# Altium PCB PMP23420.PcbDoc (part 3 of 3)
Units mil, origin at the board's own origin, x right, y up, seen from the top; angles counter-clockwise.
Board outline 5200 x 3400 mil, 6 copper layers (Top Layer, Midlayer 1, Midlayer 2, Midlayer 3, Midlayer 4, Bottom Layer), stack 61.536 mil thick; 227 components, 56 nets, 480 pads, 964 vias.
Unrouted connection lines stored in the file: 22.
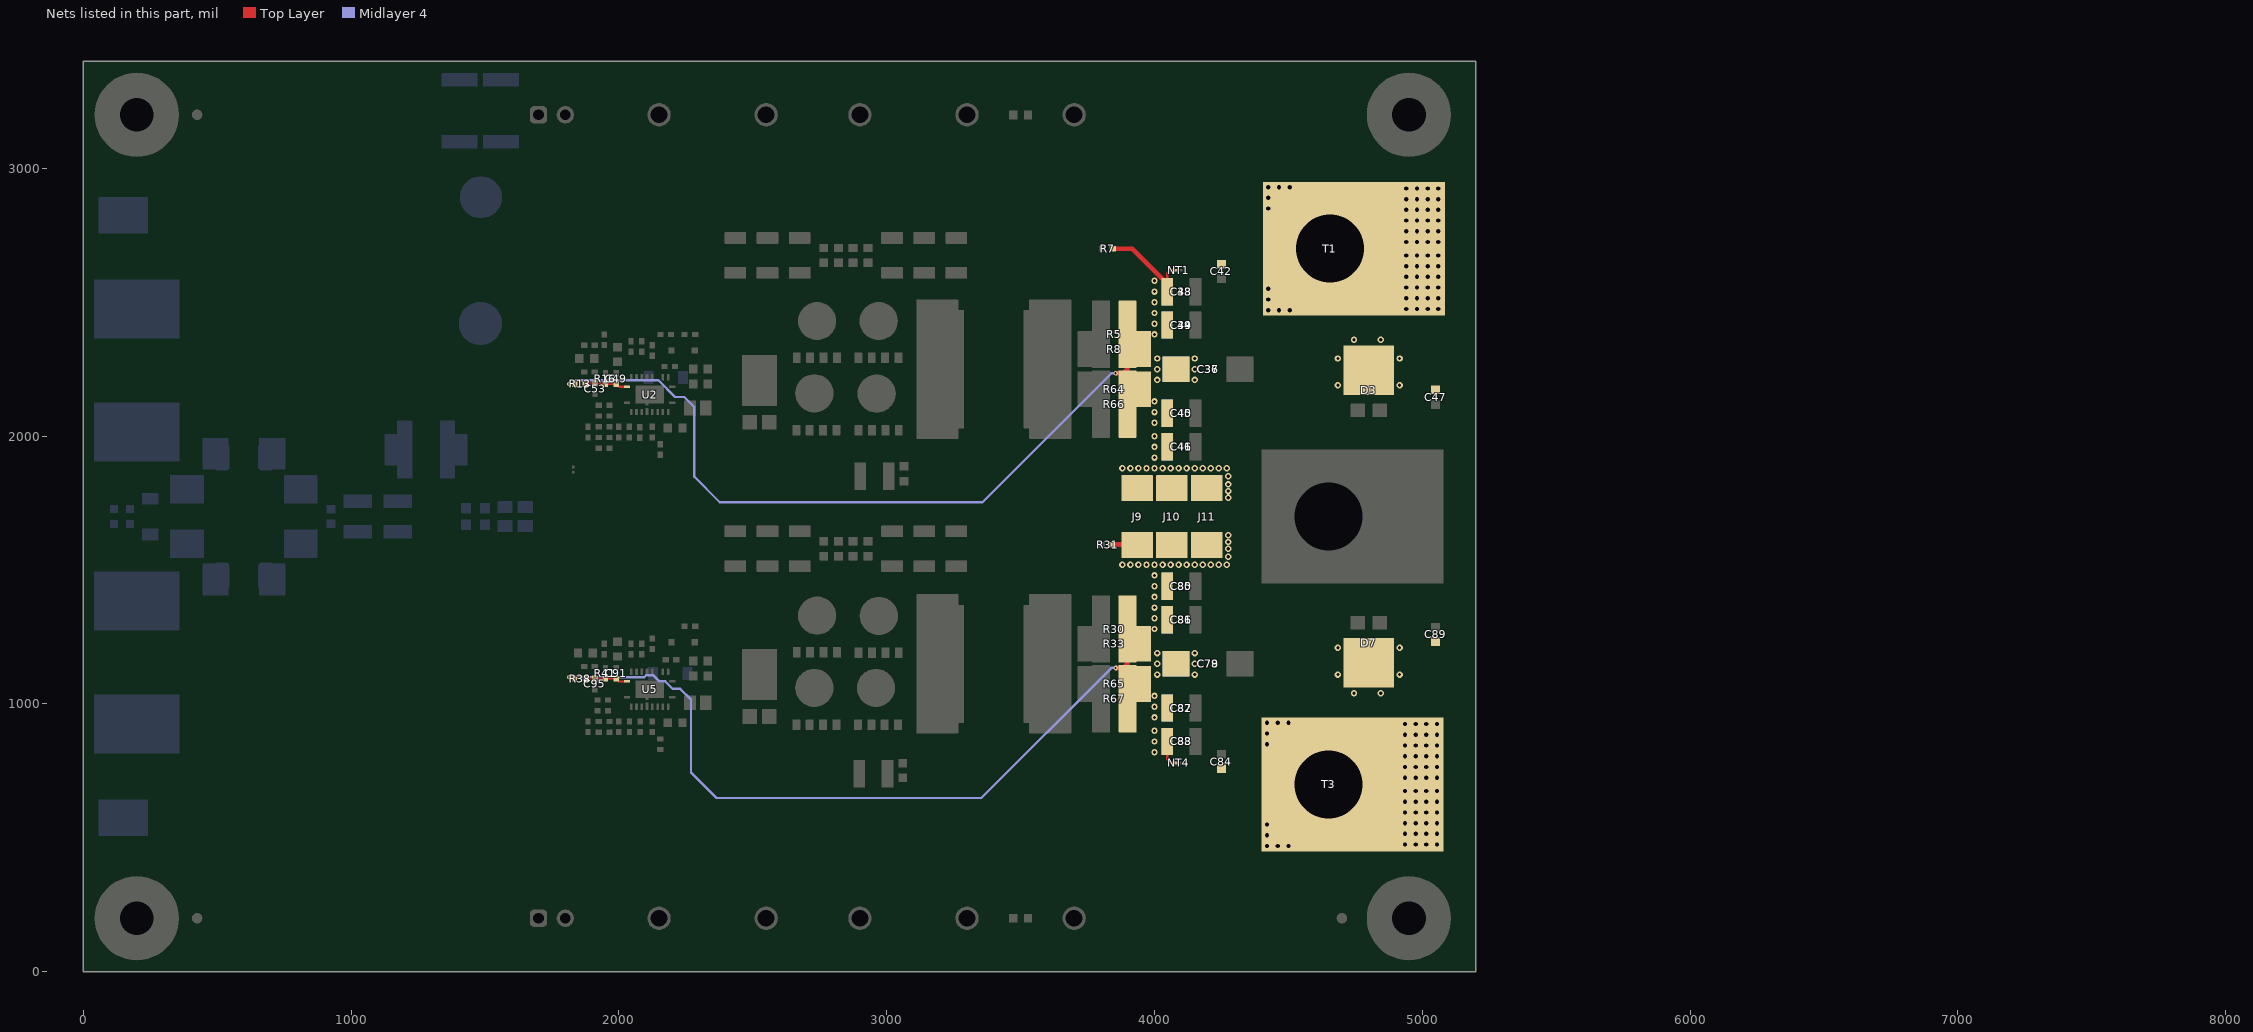
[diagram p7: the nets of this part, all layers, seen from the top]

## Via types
v1: diameter 24, hole 12, Top Layer to Bottom Layer, tented both sides, 565 vias
v2: diameter 32, hole 16, Top Layer to Bottom Layer, 174 vias
v3: diameter 18, hole 8, Top Layer to Bottom Layer, tented bottom, 88 vias
v4: diameter 18, hole 8, Top Layer to Bottom Layer, tented both sides, 71 vias
v5: diameter 24, hole 12, Top Layer to Bottom Layer, tented top, 58 vias
v6: diameter 19.68, hole 7.87, Top Layer to Bottom Layer, tented both sides, 8 vias

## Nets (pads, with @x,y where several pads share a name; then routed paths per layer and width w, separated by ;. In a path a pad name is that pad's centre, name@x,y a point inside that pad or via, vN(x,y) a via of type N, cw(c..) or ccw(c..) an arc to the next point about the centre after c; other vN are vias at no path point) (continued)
VOUT1: C36.1 C37.1 C38.1 C39.1 C40.1 C41.1 C42.1 C43.1 C44.1 C45.1 C46.1 C47.1 D3.3 J9.2 J10.2 J11.2 NT1.2 R5.2 R7.1 R8.2 R13.2 R64.2 R66.2 T1.1 | length 3018.9
  Top Layer w9: v4(1815,2195) R13.2@1835.32,2195 ; C38.1@4046.85,2540 4046.85,2569.53 4046.85,2607.11 4059.74,2620 NT1.2@4080,2620
  Top Layer w18: R7.1@3844.69,2700 3916.38,2700 C38.1@4046.85,2569.53 ; v4(3855,2235) 3884.21,2235 3899.21,2250
  Midlayer 4 w9: v4(1815,2195) 1825.16,2195 1839.15,2208.99 2147.37,2208.99 2209.99,2146.37 2244.38,2146.37 2281.58,2109.18 2281.58,1848.84 2376.87,1753.55 3357.41,1753.55 3838.86,2235 v4(3855,2235)
  other v1: 4275,1770 4275,1795 4275,1820 4275,1850 3880,1880 3910,1880 3940,1880 3970,1880 4000,1880 4030,1880 4060,1880 4090,1880 4120,1880 4150,1880 4180,1880 4210,1880 4240,1880 4270,1880 4000,1920 4000,1960 4000,2000 4000,2050 4000,2090 4000,2130 4685,2190 4915,2190 4010,2210 4150,2210 4010,2250 4150,2250 4010,2290 4150,2290 4685,2290 4915,2290 4745,2360 4845,2360 4000,2380 4000,2420 4000,2460 4000,2500 4000,2540 4000,2580
  other v2: 4425,2470 4465,2470 4505,2470 4940,2475 4980,2475 5020,2475 5060,2475 4425,2510 4940,2515 4980,2515 5020,2515 5060,2515 4425,2550 4940,2555 4980,2555 5020,2555 5060,2555 4940,2595 4980,2595 5020,2595 5060,2595 4940,2635 4980,2635 5020,2635 5060,2635 4940,2675 4980,2675 5020,2675 5060,2675 4940,2725 4980,2725 5020,2725 5060,2725 4940,2765 4980,2765 5020,2765 5060,2765 4940,2805 4980,2805 5020,2805 5060,2805 4940,2845 4980,2845 5020,2845 5060,2845 4425,2850 4940,2885 4980,2885 5020,2885 5060,2885 4425,2890 4940,2925 4980,2925 5020,2925 5060,2925 4425,2930 4465,2930 4505,2930
VOUT2: C78.1 C79.1 C80.1 C81.1 C82.1 C83.1 C84.1 C85.1 C86.1 C87.1 C88.1 C89.1 D7.3 J9.1 J10.1 J11.1 NT4.2 R30.2 R31.2 R33.2 R38.2 R65.2 R67.2 T3.1 | length 2862.5
  Top Layer w9: v4(1815,1100) 1816.72,1098.28 1832.04,1098.28 R38.2@1835.32,1095 ; J9.1@3934.19,1595 J9.1@3935,1594.19 ; C83.1@4046.85,860 4046.85,795.2 4062.05,780 NT4.2@4080,780
  Top Layer w18: R31.2@3844.69,1595 J9.1@3934.19,1595 ; v4(3855,1135) 3884.21,1135 3899.21,1150
  Midlayer 4 w9: v4(1815,1100) 1835.32,1100 1835.44,1099.88 2094.76,1099.88 2102.85,1107.96 2127.15,1107.96 2149.61,1085.5 2149.61,1084.34 2173.2,1084.34 2200.93,1056.62 2229.04,1056.62 2269.41,1016.25 2269.41,744.43 2364.87,648.98 3352.84,648.98 3838.86,1135 v4(3855,1135)
  other v1: 4000,820 4000,860 4000,900 4000,950 4000,990 4000,1030 4745,1040 4845,1040 4010,1110 4150,1110 4685,1110 4915,1110 4010,1150 4150,1150 4010,1190 4150,1190 4685,1210 4915,1210 4000,1280 4000,1320 4000,1360 4000,1400 4000,1440 4000,1480 3880,1520 3910,1520 3940,1520 3970,1520 4000,1520 4030,1520 4060,1520 4090,1520 4120,1520 4150,1520 4180,1520 4210,1520 4240,1520 4270,1520 4275,1550 4275,1580 4275,1605 4275,1630
  other v2: 4420,470 4460,470 4500,470 4935,475 4975,475 5015,475 5055,475 4420,510 4935,515 4975,515 5015,515 5055,515 4420,550 4935,555 4975,555 5015,555 5055,555 4935,595 4975,595 5015,595 5055,595 4935,635 4975,635 5015,635 5055,635 4935,675 4975,675 5015,675 5055,675 4935,725 4975,725 5015,725 5055,725 4935,765 4975,765 5015,765 5055,765 4935,805 4975,805 5015,805 5055,805 4935,845 4975,845 5015,845 5055,845 4420,850 4935,885 4975,885 5015,885 5055,885 4420,890 4935,925 4975,925 5015,925 5055,925 4420,930 4460,930 4500,930
VOUTsns1: C49.1 C53.2 R13.1 R16.1 U2.20 | length 158.4
  Top Layer w8: R13.1@1874.68,2195 1876.03,2196.34 1909.66,2196.34 C53.2@1911,2197.69 ; C53.2@1914.84,2195.16 1949.84,2195.16 R16.1@1950,2195.31 C49.1@1989.84,2195.31 ; C49.1@1989.84,2195.16 1989.84,2193.5 1995.84,2187.5 1997.5,2187.5 2000.47,2184.53 U2.20@2030.35,2184.53
VOUTsns2: C91.1 C95.2 R38.1 R41.1 U5.20 | length 156.9
  Top Layer w8: R38.1@1874.68,1095 1874.84,1094.84 1909.84,1094.84 C95.2@1910,1094.69 ; C95.2@1914.84,1095.16 1949.84,1095.16 R41.1@1950,1095.32 C91.1@1990,1095.32 C91.1@1990,1093.35 ; C91.1@1989.84,1093.19 C91.1@1990,1093.35 ; U5.20@2030.35,1084.53 1998.82,1084.53 C91.1@1990,1093.35
pads on no net: FID1.1 FID2.1 FID3.1 FID4.1 FID5.1 FID6.1 H1.1 H2.1 H3.1 H4.1 H5.0 H6.0 H7.0 H8.0 LBL1.0 SH-J1.0 SH-J2.0

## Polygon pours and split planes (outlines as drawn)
VIN on Top Layer "TOP_LAYER_Vin_Phase2" (solid, remove dead copper, pour order 71): 2624.74,1250.08 2624.74,1430.08 2589.74,1465.08 2359.74,1465.08 2359.74,1570.08 3334.74,1570.08 3334.74,1465.08 3114.74,1465.08 3079.74,1430.08 3079.74,1250.08
SW2 on Top Layer "TOP_LAYER_SW2" (solid, remove dead copper, pour order 72): 3070,1170 3070,1215 3100,1215 3100,1410 3270,1410 3270,885 3100,885 3100,955 3075,980 2620,980 2620,1005 2450,1005 2450,1215 2790,1215 2790,1170 2870,1170 2870,1215 3020,1215 3020,1170
GNDin on Top Layer "TOP_LAYER_GND_IN" (solid, remove dead copper, pour order 34): 399.45,1149.82 399.45,799.82 299.45,699.82 299.45,474.82 -0.55,474.82 -0.55,1149.82 -0.99,1149.82 -0.99,1684.82 194.01,1684.82 194.01,1655.56 454.01,1655.56 454.01,1530.56 549.01,1530.56 549.01,1149.82
+Vin_Main on Top Layer "TOP_LAYER_+Vin_Main" (solid, remove dead copper, pour order 33): 399.66,2250.58 399.66,2600.58 299.66,2700.58 299.66,2925.58 -0.34,2925.58 -0.34,1715.58 194.66,1715.58 194.66,1745.58 454.66,1745.58 454.66,1870.58 549.66,1870.58 549.66,2250.58
+Filter on Top Layer "TOP_LAYER_+Filter" (solid, remove dead copper, pour order 35): 648.74,1870.69 743.74,1870.69 743.74,1745.69 899.71,1745.69 899.71,1715.19 1234.71,1715.19 1234.71,2100.19 648.74,2100.19
VOUT2 on Top Layer "TOP_LAYER_VOUT2" (solid, remove dead copper, pour order 74): 4400,975 4675,1250 5100,1250 5100,440 3865,440 3865,1645 4290,1645 4290,1507 4085,1507 4085,1260 4115,1230 4145,1230 4175,1200 4175,1100 4145,1070 4115,1070 4085,1040 4085,775 4400,775
GND on Top Layer "TOP_LAYER_GND" (solid, remove dead copper, pour order 76): 650,1150 650,1530 745,1530 745,1655 900,1655 900,1685 1275,1685 1275,3400 5200,3400 5200,0 1325,0 1325,1150
VOUT1 on Top Layer "TOP_LAYER_VOUT1" (solid, remove dead copper, pour order 73): 4392.8,2423.55 4667.8,2148.55 5100,2148.55 5100,2958.55 3865,2958.55 3865,1753.55 4290,1753.55 4290,1893 4077.8,1893 4077.8,2138.55 4107.8,2168.55 4137.8,2168.55 4167.8,2198.55 4167.8,2298.55 4137.8,2328.55 4107.8,2328.55 4077.8,2358.55 4077.8,2623.55 4392.8,2623.55
VCC2 on Top Layer "TOP_LAYER_VCC1" (solid, remove dead copper, pour order 49): 2140,1000 2150,1000 2150,970 2170,950 2200,950 2200,910 2170,910 2140,940 2140,965
VCC1 on Top Layer "TOP_LAYER_VCC1" (solid, remove dead copper, pour order 37): 2140,2100 2150,2100 2150,2070 2170,2050 2200,2050 2200,2010 2170,2010 2140,2040 2140,2065
AGND2 on Top Layer "TOP_LAYER_AGND2" (solid, remove dead copper, pour order 43): 2135,910 2070,910 2070,875 1935,875 1935,1030 1815,1030 1815,780 2135,780
AGND1 on Top Layer "TOP_LAYER_AGND1" (solid, remove dead copper, pour order 36): 2135,2010 2070,2010 2070,1975 1935,1975 1935,2130 1815,2130 1815,1880 2135,1880
SW1 on Top Layer "TOP_LAYER_SW1" (solid, remove dead copper, pour order 39): 3070,2270 3070,2315 3100,2315 3100,2510 3270,2510 3270,1985 3100,1985 3100,2055 3075,2080 2620,2080 2620,2105 2450,2105 2450,2315 2790,2315 2790,2270 2870,2270 2870,2315 3020,2315 3020,2270
VIN on Top Layer "TOP_LAYER_Vin_Phase1" (solid, remove dead copper, pour order 38): 2625,2345 2625,2525 2590,2560 2360,2560 2360,2665 3335,2665 3335,2560 3115,2560 3080,2525 3080,2345
GNDin on Midlayer 2 "MIDLAYER_2_GND_IN" (solid, remove dead copper, pour order 42): 399.64,1150.3 399.64,800.3 299.64,700.3 299.64,475.3 -0.36,475.3 -0.36,1150.3 -0.8,1150.3 -0.8,1685.3 194.2,1685.3 194.2,1656.04 454.2,1656.04 454.2,1531.04 549.2,1531.04 549.2,1150.3
+Vin_Main on Midlayer 2 "MIDLAYER_2_+Vin_Main" (solid, remove dead copper, pour order 32): 399.72,2250.48 399.72,2600.48 299.72,2700.48 299.72,2925.48 -0.28,2925.48 -0.28,1715.48 194.72,1715.48 194.72,1745.48 454.72,1745.48 454.72,1870.48 549.72,1870.48 549.72,2250.48
+Filter on Midlayer 2 "MIDLAYER_2_+Filter" (solid, remove dead copper, pour order 44): 649.03,1870.5 744.03,1870.5 744.03,1745.5 900,1745.5 900,1715 1235,1715 1235,2100 649.03,2100
GND on Midlayer 2 "MIDLAYER_2_GND" (solid, remove dead copper, pour order 66): 650,1150 1325,1150 1325,0.88 5200,0.88 5200,3400.88 1275,3400.88 1275,1685 900,1685 900,1655 745,1655 745,1530 650,1530
VIN on Midlayer 2 "MIDLAYER_2_VIN" (solid, remove dead copper, pour order 60): 1535,750 1535,1505 1325,1715 1325,2840 3355,2840 3355,750
VOUT1 on Midlayer 2 "MIDLAYER_2_VOUT1" (solid, remove dead copper, pour order 64): 4392.5,2422.5 4667.5,2147.5 5100,2147.5 5100,2957.5 3865,2957.5 3865,1752.5 4290,1752.5 4290,1895 4077.5,1895 4077.5,2137.5 4107.5,2167.5 4137.5,2167.5 4167.5,2197.5 4167.5,2297.5 4137.5,2327.5 4107.5,2327.5 4077.5,2357.5 4077.5,2622.5 4392.5,2622.5
VOUT2 on Midlayer 2 "MIDLAYER_2_VOUT2" (solid, remove dead copper, pour order 65): 4400,975 4675,1250 5100,1250 5100,440 3865,440 3865,1645 4290,1645 4290,1505 4085,1505 4085,1260 4115,1230 4145,1230 4175,1200 4175,1100 4145,1070 4115,1070 4085,1040 4085,775 4400,775
VIN on Bottom Layer "BOTTOM_LAYER_Vin_Phase2" (solid, remove dead copper, pour order 57): 2625,1250 2625,1430 2590,1465 2360,1465 2360,1570 3335,1570 3335,1465 3115,1465 3080,1430 3080,1250
VIN on Bottom Layer "BOTTOM_LAYER_Vin_Phase1" (solid, remove dead copper, pour order 56): 2624.94,2345.22 2624.94,2525.22 2589.94,2560.22 2359.94,2560.22 2359.94,2665.22 3334.94,2665.22 3334.94,2560.22 3114.94,2560.22 3079.94,2525.22 3079.94,2345.22
+Filter on Bottom Layer "BOTTOM_LAYER_+Filter" (solid, remove dead copper, pour order 48): 648.28,1870.96 743.28,1870.96 743.28,1745.96 899.25,1745.96 899.25,1715 1235,1715 1235,2100.46 648.28,2100.46
VOUT2 on Bottom Layer "BOTTOM_LAYER_VOUT2" (solid, remove dead copper, pour order 70): 4400,975 4675,1250 5100,1250 5100,440 3865,440 3865,1645 4260,1645 4260,1535 4085,1535 4085,1260 4115,1230 4145,1230 4175,1200 4175,1100 4145,1070 4115,1070 4085,1040 4085,775 4400,775
VOUT1 on Bottom Layer "BOTTOM_LAYER_VOUT1" (solid, remove dead copper, pour order 63): 4392.8,2423.55 4667.8,2148.55 5100,2148.55 5100,2958.55 3865,2958.55 3865,1753.55 4257.8,1753.55 4257.8,1863.55 4077.8,1863.55 4077.8,2138.55 4107.8,2168.55 4137.8,2168.55 4167.8,2198.55 4167.8,2298.55 4137.8,2328.55 4107.8,2328.55 4077.8,2358.55 4077.8,2623.55 4392.8,2623.55
GND on Bottom Layer "BOTTOM_LAYER_GND" (solid, remove dead copper, pour order 75): 650,1150 1325,1150 1325,0 5200,0 5200,3400 1275,3400 1275,1685 899.33,1685 899.33,1655.08 745,1655.08 745,1530.08 650,1530.08
GNDin on Bottom Layer "BOTTOM_LAYER_GND_IN" (solid, remove dead copper, pour order 47): 400,1150 400,800 300,700 300,475 0,475 0,1150 -0.44,1150 -0.44,1685 194.56,1685 194.56,1655.74 454.56,1655.74 454.56,1530.74 549.56,1530.74 549.56,1150
+Vin_Main on Bottom Layer "BOTTOM_LAYER_+Vin_Main" (solid, remove dead copper, pour order 45): 400,2250 400,2600 300,2700 300,2925 0,2925 0,1715 195,1715 195,1745 455,1745 455,1870 550,1870 550,2250
GNDin on Midlayer 4 "MIDLAYER_4_GND_IN" (solid, remove dead copper, pour order 51): 400,1150 400,800 300,700 300,475 0,475 0,1150 -0.44,1150 -0.44,1685 194.56,1685 194.56,1655.74 454.56,1655.74 454.56,1530.74 549.56,1530.74 549.56,1150
+Filter on Midlayer 4 "MIDLAYER_4_+Filter" (solid, remove dead copper, pour order 58): 648.47,1870.89 743.47,1870.89 743.47,1745.89 899.44,1745.89 899.44,1715 1235,1715 1235,2100.39 648.47,2100.39
GND on Midlayer 4 "MIDLAYER_4_GND" (solid, remove dead copper, pour order 62): 650,1150.44 1325,1150.44 1325,0.44 5200,0.44 5200,3400.44 1275,3400.44 1275,1685 899.07,1685 899.07,1655.52 745,1655.52 745,1530.52 650,1530.52
+Vin_Main on Midlayer 4 "MIDLAYER_4_+Vin_Main" (solid, remove dead copper, pour order 50): 400,2250 400,2600 300,2700 300,2925 0,2925 0,1715 195,1715 195,1745 455,1745 455,1870 550,1870 550,2250
GNDin on Midlayer 3 "MIDLAYER_3_GND_IN" (solid, remove dead copper, pour order 52): 400,1150 400,800 300,700 300,475 0,475 0,1150 -0.44,1150 -0.44,1685 194.56,1685 194.56,1655.74 454.56,1655.74 454.56,1530.74 549.56,1530.74 549.56,1150
+Filter on Midlayer 3 "MIDLAYER_3_+Filter" (solid, remove dead copper, pour order 53): 649.03,1870.5 744.03,1870.5 744.03,1745.5 900,1745.5 900,1715 1235,1715 1235,2100 649.03,2100
GND on Midlayer 3 "MIDLAYER_3_GND" (solid, remove dead copper, pour order 59): 650,1150.06 1325,1150.06 1325,0.06 5200,0.06 5200,3400.06 1275,3400.06 1275,1685 898.86,1685 898.86,1655.15 745,1655.15 745,1530.15 650,1530.15
+Vin_Main on Midlayer 3 "MIDLAYER_3_+Vin_Main" (solid, remove dead copper, pour order 46): 400,2250 400,2600 300,2700 300,2925 0,2925 0,1715 195,1715 195,1745 455,1745 455,1870 550,1870 550,2250
GNDin on Midlayer 1 "MIDLAYER_1_GND_IN" (solid, remove dead copper, pour order 67): 399.46,1149.97 399.46,799.97 299.46,699.97 299.46,474.97 -0.54,474.97 -0.54,1149.97 -0.99,1149.97 -0.99,1684.97 194.01,1684.97 194.01,1655.71 454.01,1655.71 454.01,1530.71 549.01,1530.71 549.01,1149.97
+Vin_Main on Midlayer 1 "MIDLAYER_1_+Vin_Main" (solid, remove dead copper, pour order 61): 399.68,2250.58 399.68,2600.58 299.68,2700.58 299.68,2925.58 -0.32,2925.58 -0.32,1715.58 194.68,1715.58 194.68,1745.58 454.68,1745.58 454.68,1870.58 549.68,1870.58 549.68,2250.58
+Filter on Midlayer 1 "MIDLAYER_1_+Filter" (solid, remove dead copper, pour order 68): 648.8,1870.66 743.8,1870.66 743.8,1745.66 899.77,1745.66 899.77,1715.16 1234.77,1715.16 1234.77,2100.16 648.8,2100.16
GND on Midlayer 1 "MIDLAYER_1_GND" (solid, remove dead copper, pour order 69): 650,1150 1325,1150 1325,2.26 5200,2.26 5200,3402.26 1275,3402.26 1275,1685 900,1685 900,1655 745,1655 745,1530 650,1530

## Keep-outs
Keep-Out Layer:
  text ".Layer_Name" at 577,-858.49 h60

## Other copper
Top Layer:
  rectangle net GND: 2460,890 2590,980
  rectangle net GND: 2460,1990 2590,2080
  pour cut-out: 3062.54,946.07 3062.54,961.07 3017.54,961.07 3017.54,946.07
  pour cut-out: 3065,2045 3065,2060 3020,2060 3020,2045
  pour cut-out: 3069.18,2261.07 3079.18,2271.07 3079.18,2316.07 3009.18,2316.07 3009.18,2271.07 3019.18,2261.07
  pour cut-out: 2839.18,2261.07 2849.18,2271.07 2849.18,2316.07 2779.18,2316.07 2779.18,2271.07 2789.18,2261.07
  pour cut-out: 2839.18,1161.07 2849.18,1171.07 2849.18,1216.07 2779.18,1216.07 2779.18,1171.07 2789.18,1161.07
  pour cut-out: 3070,1160 3080,1170 3080,1215 3010,1215 3010,1170 3020,1160
  pour cut-out: 2174,2332 2232,2332 2232,2280 2306,2280 2306,2360 2184,2360 2165,2341 2141,2341 2141,2226 2130,2215 2130,2190 2160,2190 2160,2271 2174,2285
  pour cut-out: 2306,1200 2240,1200 2240,1244 2182,1244 2160,1222 2160,1090 2130,1090 2130,1115 2144.84,1129.84 2144.84,1240.84 2177,1273 2306,1273
  pour cut-out: 2360,2663 3335,2663 3335,2687 2360,2687
  pour cut-out: 2360,1568 3335,1568 3335,1592 2360,1592
  pour cut-out: 3835,1420 3865,1420 3865,880 3835,880
  pour cut-out: 3835,2520 3865,2520 3865,1980 3835,1980
  pour cut-out: 3120,1415 3120,1460 3680,1460 3680,1415 3505,1415 3505,885 3680,885 3680,840 3120,840 3120,880 3295,880 3295,1415
  pour cut-out: 3120,2515 3120,2560 3680,2560 3680,2515 3505,2515 3505,1985 3680,1985 3680,1940 3120,1940 3120,1980 3295,1980 3295,2515
  region net NetL4_2: 3835,1990 3530,1990 3530,2510 3835,2510
  region net NetL6_2: 3835,890 3530,890 3530,1410 3835,1410
  text ".Layer_Name" at 577,-858.49 h60
Bottom Layer:
  rectangle net NetC1_1: 1325,2765 1645,3130
  pour cut-out: 1315,1715 1315,1685 1710,1685 1710,1715 1540,1715
  pour cut-out: 2360,1568 3335,1568 3335,1592 2360,1592
  pour cut-out: 2360,2663 3335,2663 3335,2687 2360,2687
  pour cut-out: 1645,3010 1830,3010 1830,2305 1690,2305 1690,2575 1305,2575 1305,2765 1645,2765
  region net VIN: 1325,1715 1325,2575 1690,2575 1690,1715
  text ".Layer_Name" at 577,-858.49 h60

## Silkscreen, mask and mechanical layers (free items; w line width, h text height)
Top Overlay:
  lines w5.91: 3127.28,2525.28 3127.28,2549.21 ; 3132.28,1425.28 3132.28,1449.21 ; 3668,1425 3668,1448.93 ; 3668,2525 3668,2548.93
  lines w6: 1853,1086 1857,1086 ; 1853,1104 1857,1104 ; 1853,2186 1857,2186 ; 1853,2204 1857,2204 ; 1876,913 1876,917 ; 1876,2013 1876,2017 ; 1888,1131 1892,1131 ; 1888,1149 1892,1149 ; 1888,2231 1892,2231 ; 1888,2249 1892,2249 ; 1888,2331 1892,2331 ; 1888,2349 1892,2349 ; 1894,913 1894,917 ; 1894,2013 1894,2017 ; 1901,1073 1901,1077 ; 1902,2176 1902,2180 ; 1919,1073 1919,1077 ; 1920,2176 1920,2180 ; 1936,1203 1936,1207 ; 1936,2358 1936,2362 ; 1938,966 1942,966 ; 1938,984 1942,984 ; 1938,1006 1942,1006 ; 1938,1024 1942,1024 ; 1941,1113 1941,1117 ; 1941,2213 1941,2217 ; 1943,886 1947,886 ; 1943,904 1947,904 ; 1943,926 1947,926 ; 1943,944 1947,944 ; 1943,1946 1947,1946 ; 1943,1964 1947,1964 ; 1943,1986 1947,1986 ; 1943,2004 1947,2004 ; 1943,2026 1947,2026 ; 1943,2044 1947,2044 ; 1943,2066 1947,2066 ; 1943,2084 1947,2084 ; 1943,2106 1947,2106 ; 1943,2124 1947,2124 ; 1954,1203 1954,1207 ; 1954,2358 1954,2362 ; 1959,1113 1959,1117 ; 1959,2213 1959,2217 ; 1981,1113 1981,1117 ; 1981,2213 1981,2217 ; 1991,913 1991,917 ; 1991,2013 1991,2017 ; 1999,1113 1999,1117 ; 1999,2213 1999,2217 ; 2009,913 2009,917 ; 2009,2013 2009,2017 ; 2031,913 2031,917 ; 2031,2013 2031,2017 ; 2036,1203 2036,1207 ; 2036,2333 2036,2337 ; 2049,913 2049,917 ; 2049,2013 2049,2017 ; 2054,1203 2054,1207 ; 2054,2333 2054,2337 ; 2071,913 2071,917 ; 2071,2013 2071,2017 ; 2076,1203 2076,1207 ; 2076,2333 2076,2337 ; 2089,913 2089,917 ; 2089,2013 2089,2017 ; 2094,1203 2094,1207 ; 2094,2333 2094,2337 ; 2116,913 2116,917 ; 2116,1223 2116,1227 ; 2116,2013 2116,2017 ; 2116,2318 2116,2322 ; 2134,913 2134,917 ; 2134,1223 2134,1227 ; 2134,2013 2134,2017 ; 2134,2318 2134,2322 ; 2146,848 2146,852 ; 2146,1948 2146,1952 ; 2164,848 2164,852 ; 2164,1948 2164,1952 ; 2173,2371 2177,2371 ; 2173,2389 2177,2389 ; 2188,2251 2192,2251 ; 2188,2269 2192,2269 ; 2193,1156 2197,1156 ; 2193,1174 2197,1174 ; 2263,1281 2267,1281 ; 2263,1299 2267,1299 ; 2263,2371 2267,2371 ; 2263,2389 2267,2389 ; 3823,1586 3827,1586 ; 3823,1604 3827,1604 ; 3823,2691 3827,2691 ; 3823,2709 3827,2709
  text "'.PRJ_Number'.PCB_Rev" at 675,330 h108.27
  text ".Layer_Name" at 577,-858.49 h60
Bottom Overlay:
  circle w20: c400,1485 r10
  lines w6: 1147.91,2020.09 1147.91,2086.02 ; 1412.09,2020.09 1412.09,2086.02
  text ".Layer_Name" at 577,-858.49 h60
Top Paste:
  text ".Layer_Name" at 577,-858.49 h60
Bottom Paste:
  text ".Layer_Name" at 577,-858.49 h60
Top Solder:
  region: 3990,1406 3866,1406 3866,894 3990,894
  rectangle: 3709.9,894 3834,1406
  rectangle: 3710,1994 3834,2506
  region: 3989.91,2506 3866,2506 3866,1994 3989.91,1994
  text ".Layer_Name" at 577,-858.49 h60
  text ".Layer_Name" at 577,-858.49 h60
Bottom Solder:
  text ".Layer_Name" at 577,-858.49 h60
Drill Guide:
  text ".Layer_Name" at 577,-858.49 h60
M1 Board Outline:
  the board outline again, w10
  text ".Layer_Name" at 577,-858.49 h60
M2 Board Dimensions:
  rectangle: 125,-400 500,-275
  rectangle: 0,-275 125,-150
  lines w7: 0,-275 1000,-275 ; 125,-400 125,-150 ; 250,-400 250,-150 ; 500,-400 500,-150 ; 750,-400 750,-150 ; 0,-400 0,-150 1000,-150 1000,-400 0,-400
  text ".Layer_Name" at 577,-858.49 h60
M3 3D STEP Top:
  text ".Layer_Name" at 577,-858.49 h60
M4 3D STEP Bottom:
  text ".Layer_Name" at 577,-858.49 h60
M5 Assembly Top:
  lines w10: -292,-930.17 6308,-930.17 ; -292,-726.83 6310,-726.83 ; -292,-523.5 -292,-1133.5 3713,-1133.5 6310,-1133.5 6310,-523.5 -291.5,-523.5 -291.5,-1133.5 1284,-1133.5 ; 2173,-1133.5 2173,-523.5 ; 3440,-726.83 3440,-523.5 ; 4280,-726.83 4280,-523.5 ; 4902,-1140 4902,-937.17
  text "COMPONENTS MARKED 'DNP' SHOULD NOT BE POPULATED." at 1153.5,-318.5 h60
  text "ASSEMBLY VARIANT:" at 1153,-434 h60
  text ".VariantName" at 2189,-434 h60
  text "PCB VIEWED FROM TOP SIDE" at -228.5,-655.67 h60
  text "BOARD #:" at 2248,-655.67 h60
  text ".PRJ_Number" at 2793.5,-655.67 h60
  text "REV:" at 3638,-655.67 h60
  text ".PCB_Rev" at 3929.5,-655.67 h60
  text "SVN REV:" at 4476,-655.67 h60
  text ".VersionControl_RevNumber" at 4982,-655.67 h60
  text "PLOT NAME =" at -228.5,-1064.34 h60
  text ".plot_File_Name" at 577,-1064.34 h60
  text "GENERATED    :" at 2250,-1064.34 h60
  text ".Print_Date" at 3119.5,-1064.34 h60
  text ".Print_Time" at 3848.5,-1064.34 h60
  text "TEXAS INSTRUMENTS" at 5113,-1064.34 h60
M6 Assembly Bottom:
  lines w10: -292.5,-727.33 6309.5,-727.33 ; -290.5,-930.67 6309.5,-930.67 ; 1115.5,-1140.5 1115.5,-937.67 ; 1737.5,-727.33 1737.5,-524 ; 2577.5,-727.33 2577.5,-524 ; 3844.5,-1134 3844.5,-524 ; 4733.5,-1134 6309,-1134 6309,-524 -292.5,-524 -292.5,-1134 2304.5,-1134 6309.5,-1134 6309.5,-524
  text "COMPONENTS MARKED 'DNP' SHOULD NOT BE POPULATED." at 6102,-318 h60
  text ".VariantName" at 5058,-434 h60
  text "ASSEMBLY VARIANT:" at 6097,-434 h60
  text ".VersionControl_RevNumber" at 1035.5,-656.17 h60
  text "SVN REV:" at 1541.5,-656.17 h60
  text ".PCB_Rev" at 2088,-656.17 h60
  text "REV:" at 2379.5,-656.17 h60
  text ".PRJ_Number" at 3224,-656.17 h60
  text "BOARD #:" at 3769.5,-656.17 h60
  text "PCB VIEWED FROM BOTTOM SIDE" at 6246,-656.17 h60
  text "TEXAS INSTRUMENTS" at 904.5,-1064.84 h60
  text ".Print_Time" at 2169,-1064.84 h60
  text ".Print_Date" at 2898,-1064.84 h60
  text "GENERATED    :" at 3767.5,-1064.84 h60
  text ".plot_File_Name" at 5440.5,-1064.84 h60
  text "PLOT NAME =" at 6246,-1064.84 h60
M9 Title Sheet:
  drawing of 56 lines, arcs and shapes, not listed
  text "1" at 1058.34,13381.39 h70
  text "2" at 4384,13381.39 h70
  text "3" at 7714,13381.39 h70
  text "4" at 11049,13381.39 h70
  text "5" at 14374,13381.39 h70
  text "6" at 17709,13381.39 h70
  text "A" at -463,11603.39 h70
  text "A" at 19237,11603.39 h70
  text "B" at -463,7853.39 h70
  text "B" at 19237,7853.39 h70
  text "C" at -463,4103.39 h70
  text "C" at 19237,4103.39 h70
  text "D" at -463,353.39 h70
  text "D" at 19237,353.39 h70
  text "PROJECT TITLE:" at 16143,268.39 h45
  text ".PRJ_Title" at 16193,135.06 h70
  text "DESIGNED FOR:" at 16143,-32.61 h45
  text ".PRJ_Customer" at 16193,-172.61 h70
  text "FILE NAME:" at 16143,-332.61 h45
  text ".PCB_File_Name_No_Path" at 16193,-452.61 h70
  text "Texas Instruments (TI) and/or its licensors do not warrant the accuracy or completeness of this specification" at 11173.5,-614.45 h45
  text "ENGINEER:" at 16143,-622.61 h45
  text "LAYOUT BY:" at 17648,-622.61 h45
  text "or any information contained therein. TI and/or its licensors do not warrant that this design will meet" at 11128.51,-727.11 h45
  text ".PRJ_Engineer" at 16193,-777.6 h70
  text ".PCB_Layout" at 17698.5,-777.6 h70
  text "the specifications, will be suitable for your application or fit for any particular purpose, or will operate in" at 11128.51,-839.78 h45
  text ".Layer_Name" at 577,-858.49 h60
  text "ALTIUM DESIGNER VERSION:" at 17648,-932.61 h45
  text "an implementation. TI and/or its licensors do not warrant that the design is production worthy. You should" at 11128.51,-952.44 h45
  text "completely validate and test your design implementation to confirm the system functionality for your application." at 11173.5,-1065.11 h45
  text ".print_Scale" at 16193,-1065.94 h70
  text ".Application_BuildNumber" at 17698.5,-1065.94 h70
  text "1" at 1058.34,-1318.61 h70
  text "2" at 4384,-1318.61 h70
  text "3" at 7714,-1318.61 h70
  text "4" at 11049,-1318.61 h70
  text "5" at 14374,-1318.61 h70
  text "6" at 17709,-1318.61 h70
M10 Fab Notes:
  drawing of 189 lines, arcs and shapes, not listed
  text "DESIGN INFORMATION" at 17178.02,6365.17 h60
  text "MIN. TRACK WIDTH:" at 16533.46,6233.05 h60
  text "6" at 17629.7,6233.05 h60
  text "MIL" at 17784.46,6233.05 h60
  text "MIN. CLEARANCE:" at 16533.46,6108.92 h60
  text "MIL" at 17784.46,6108.92 h60
  text "7.874" at 17459.65,6104.33 h60
  text "MIN. VIA PAD SIZE:" at 16533.46,5984.8 h60
  text "18" at 17599.71,5984.8 h60
  text "MIL" at 17784.46,5984.8 h60
  text "0.127mm (5MIL)" at 17228.46,5854.9 h60
  text "MINIMUM ANNULAR RING" at 16204.23,5846.67 h60
  text "EXTERNAL" at 17936.46,5846.67 h60
  text "PER" at 16404.23,5736.55 h60
  text "IPC-D-275 CLASS 2 LEVEL C" at 16624.23,5736.54 h60
  text "MIL, HOLES" at 18112.46,5636.07 h60
  text "+/-" at 17720,5627.48 h60
  text "+/-" at 18574,5627.48 h60
  text "REGISTRATION TOLERANCES:" at 16204.23,5626.42 h60
  text "METAL" at 17404,5626.42 h60
  text "5" at 17980.2,5626.42 h60
  text "3" at 18813.2,5626.42 h60
  text "MIL" at 18929.46,5626.42 h60
  text "HOLE SIZE TOLERANCE (UNLESS OTHERWISE SPECIFIED):" at 16204.23,5528.1 h60
  text "+/-" at 18574,5525.23 h60
  text "3" at 18813.2,5524.17 h60
  text "MIL" at 18929.46,5524.17 h60
  text "MATERIAL:" at 16129.46,5386.52 h60
  text "FR-4 High Tg" at 17115.9,5258 h60
  text "X" at 16971.46,5250.01 h60
  text "FR-4" at 16550.46,5245.49 h60
  text "OTHER" at 18038.46,5245.49 h60
  text "62 MIL (1.6mm) +/-10%" at 16870.56,5102.46 h60
  text "X" at 16750.46,5100.01 h60
  text "THICKNESS:" at 16204.23,5094.24 h60
  text "OTHER" at 18155.46,5094.24 h60
  text "TOLERANCE:" at 16204.23,4955.92 h60
  text "X" at 17052.46,4955.92 h60
  text "ANSI IPC-6012 TYPE 3 CLASS 2" at 17230.48,4955.92 h60
  text "OTHER +/-" at 17230.46,4811.73 h60
  text "BOW & TWIST:" at 16204.23,4666.54 h60
  text "X" at 17052.46,4666.54 h60
  text "ANSI IPC-6012 TYPE 3 CLASS 2" at 17230.48,4666.54 h60
  text "OTHER +/-" at 17230.46,4519.85 h60
  text "DRILLING:" at 16129.46,4389.23 h60
  text "NC_DRILL FILES" at 17890.46,4284.04 h60
  text "REFERENCE:" at 16204.23,4280.1 h60
  text "X" at 16861.46,4280.01 h60
  text "AS SHOWN" at 17039.46,4280.1 h60
  text "X" at 17762.46,4280.1 h60
  text "OTHER" at 18188.46,4137.85 h60
  text "PTH COPPER THICKNESS:" at 16203.91,4134.32 h60
  text "X" at 17343.14,4134.32 h60
  text "20-30 um" at 17471.14,4134.32 h60
  text "BOARD FINISH:" at 16129.46,3986.73 h60
  text "SILKSCREEN:" at 16284.68,3876.6 h60
  text "X" at 17242.46,3876.6 h60
  text "TOP" at 17359.46,3876.6 h60
  text "X" at 17752.46,3876.6 h60
  text "BOTTOM" at 17870.46,3876.6 h60
  text "SILKSCREEN COLOR:" at 16284.68,3721.41 h60
  text "X" at 17241.46,3721.41 h60
  text "WHITE" at 17359.46,3721.41 h60
  text "OTHER" at 17870.46,3721.41 h60
  text "X" at 17372.46,3577.96 h60
  text "GREEN" at 17490.46,3577.96 h60
  text "OTHER" at 18108.46,3577.96 h60
  text "SOLDER RESIST COLOR:" at 16284.68,3571.1 h60
  text "X" at 17372.46,3423.71 h60
  text "MATTE" at 17490.46,3423.71 h60
  text "SEMI-GLOSS" at 18108,3423.07 h60
  text "IMMERSION GOLD (ENIG)" at 17190.46,3250.94 h60
  text "ENEPIG" at 18528,3243.72 h60
  text "SURFACE FINISH:" at 16129.46,3242.72 h60
  text "X" at 17012.46,3242.72 h60
  text "IMM. TIN/SILVER OR EQUIV" at 16459,3105.4 h60
  text "OTHER" at 17890.46,3101.47 h60
  text "ARRAY/PANEL:" at 16129.46,2946.09 h60
  text "X" at 17012.46,2937.87 h60
  text "CUT AND TRIM PER M1 BOARD OUTLINE" at 17190.46,2937.87 h60
  text "N.C. ROUTE" at 17190.46,2801.9 h60
  text "V. SCORE" at 18056.46,2801.9 h60
  text "CERTIFICATION:" at 16129.46,2672.77 h60
  text "MATERIALS AND WORKMANSHIP FOR ALL PCBS" at 16854.46,2672.77 h60
  text "TO MEET OR EXCEED THE REQUIREMENTS OF:" at 16854.46,2578.71 h60
  text "X" at 16491.97,2450.08 h60
  text "ANSI IPC-A-600F CLASS ->" at 16619.96,2450.08 h60
  text "X" at 18267.97,2450.08 h60
  text "2" at 18377.96,2450.08 h60
  text "1" at 18062.96,2448.58 h60
  text "3" at 18731.96,2448.58 h60
  text "X" at 17303.97,2302.39 h60
  text "RoHS" at 17431.96,2302.39 h60
  text "OTHER" at 18076.36,2302.39 h60
  text "PER ORDER" at 18473.42,2302.39 h60
  text "ALL BOARDS MUST MEET OR EXCEED UL94-V0 REQUIREMENTS." at 16157,2148.57 h60
  text "PCB MUST BEAR THE UL94V-0 UL REGISTERED MATERIAL ID NUMBER" at 16157,2032.5 h60
  text "ADDITIONAL REQUIREMENTS:" at 16129.46,1863.08 h60
  text "MICROSECTION:" at 16204.23,1755.95 h60
  text "YES" at 17109.96,1755.95 h60
  text "REQUIRED" at 17971.46,1611.62 h60
  text "BARE BOARD ELEC. TEST:" at 16204.23,1608.76 h60
  text "NONE" at 17509.96,1608.76 h60
  text "X" at 17853.46,1608.76 h60
  text "PER ORDER" at 18563.46,1608.76 h60
  text "XX MIL VIAS REQUIRE NON-CONDUCTIVE FILL AND PLANARIZE" at 16372.38,1403.82 h59
  text "XX MIL VIAS REQUIRE CONDUCTIVE FILL AND PLANARIZE" at 16380.38,1299.84 h60
  text "OUTER XX MIL TRACES REQUIRE 50 OHM SINGLE-ENDED IMPEDANCE" at 16379.39,1136.46 h58
  text "LAYER 2 & 3 (INNER LAYERS) XX MIL WIDE, XX MIL SPACE / TRACES REQUIRE 100 OHM DIFFERENTIAL IMPEDANCE" at 16371.39,900.74 h60
  text ".Layer_Name" at 577,-858.49 h60
M11 Gerber Information:
  lines w10: -292,-930.17 6308,-930.17 ; -292,-726.83 6310,-726.83 ; -292,-523.5 -292,-1133.5 3713,-1133.5 6310,-1133.5 6310,-523.5 -291.5,-523.5 -291.5,-1133.5 1284,-1133.5 ; 2173,-1133.5 2173,-523.5 ; 3440,-726.83 3440,-523.5 ; 4280,-726.83 4280,-523.5 ; 4902,-1140 4902,-937.17
  text "ALL ARTWORK VIEWED FROM TOP SIDE" at -228.5,-655.67 h60
  text "BOARD #:" at 2248,-655.67 h60
  text ".PRJ_Number" at 2793.5,-655.67 h60
  text "REV:" at 3638,-655.67 h60
  text ".PCB_Rev" at 3929.5,-655.67 h60
  text "SVN REV:" at 4476,-655.67 h60
  text ".VersionControl_RevNumber" at 4982,-655.67 h60
  text "LAYER NAME =" at -228.5,-858.49 h60
  text "PLOT NAME =" at -228.5,-1064.34 h60
  text ".plot_File_Name" at 577,-1064.34 h60
  text "GENERATED    :" at 2250,-1064.34 h60
  text ".Print_Date" at 3119.5,-1064.34 h60
  text ".Print_Time" at 3848.5,-1064.34 h60
  text "TEXAS INSTRUMENTS" at 5113,-1064.34 h60
M12 Stackup:
  drawing of 399 lines, arcs and shapes, not listed
  text "Layer" at 14605.06,13091.48 h60
  text "Name" at 15014.97,13091.48 h60
  text "Material" at 15944.72,13091.48 h60
  text "Thickness" at 16804.48,13091.48 h60
  text "Constant" at 17454.32,13091.48 h60
  text "Board Layer Stack" at 18024.18,13091.48 h60
  text "Top Overlay" at 15014.97,12971.48 h60
  text "Top Solder" at 15014.97,12851.48 h60
  text "Solder Resist" at 15944.72,12851.48 h60
  text "0.40mil" at 16804.48,12851.48 h60
  text "3.5" at 17454.32,12851.48 h60
  text "1" at 14605.06,12731.48 h60
  text "Top Layer" at 15014.97,12731.48 h60
  text "CF-005" at 15944.72,12731.48 h60
  text "2.76mil" at 16804.48,12731.48 h60
  text "Dielectric 1" at 15014.97,12611.48 h60
  text "PP-023" at 15944.72,12611.48 h60
  text "9.00mil" at 16804.48,12611.48 h60
  text "4.5" at 17454.32,12611.48 h60
  text "2" at 14605.06,12491.48 h60
  text "Midlayer 1" at 15014.97,12491.48 h60
  text "CF-004" at 15944.72,12491.48 h60
  text "2.76mil" at 16804.48,12491.48 h60
  text "Dielectric 2" at 15014.97,12371.48 h60
  text "PP-023" at 15944.72,12371.48 h60
  text "9.00mil" at 16804.48,12371.48 h60
  text "4.5" at 17454.32,12371.48 h60
  text "3" at 14605.06,12251.48 h60
  text "Midlayer 2" at 15014.97,12251.48 h60
  text "CF-004" at 15944.72,12251.48 h60
  text "2.76mil" at 16804.48,12251.48 h60
  text "Dielectric3" at 15014.97,12131.48 h60
  text "Core-034" at 15944.72,12131.48 h60
  text "9.00mil" at 16804.48,12131.48 h60
  text "4.6" at 17454.32,12131.48 h60
  text "4" at 14605.06,12011.48 h60
  text "Midlayer 3" at 15014.97,12011.48 h60
  text "CF-004" at 15944.72,12011.48 h60
  text "2.76mil" at 16804.48,12011.48 h60
  text "Dielectric 4" at 15014.97,11891.48 h60
  text "PP-023" at 15944.72,11891.48 h60
  text "9.00mil" at 16804.48,11891.48 h60
  text "4.5" at 17454.32,11891.48 h60
  text "5" at 14605.06,11771.48 h60
  text "Midlayer 4" at 15014.97,11771.48 h60
  text "CF-004" at 15944.72,11771.48 h60
  text "2.76mil" at 16804.48,11771.48 h60
  text "Dielectric 5" at 15014.97,11651.48 h60
  text "PP-023" at 15944.72,11651.48 h60
  text "9.00mil" at 16804.48,11651.48 h60
  text "4.5" at 17454.32,11651.48 h60
  text "6" at 14605.06,11531.48 h60
  text "Bottom Layer" at 15014.97,11531.48 h60
  text "CF-005" at 15944.72,11531.48 h60
  text "2.76mil" at 16804.48,11531.48 h60
  text "Bottom Solder" at 15014.97,11411.48 h60
  text "Solder Resist" at 15944.72,11411.48 h60
  text "0.40mil" at 16804.48,11411.48 h60
  text "3.5" at 17454.32,11411.48 h60
  text "Bottom Overlay" at 15014.97,11291.48 h60
  text ".Layer_Name" at 577,-858.49 h60
M13 Component Bodies Top:
  text ".Layer_Name" at 577,-858.49 h60
M14 Component Bodies Bottom:
  text ".Layer_Name" at 577,-858.49 h60
M15 Courtyards Top:
  text ".Layer_Name" at 577,-858.49 h60
M16 Courtyards Bottom:
  text ".Layer_Name" at 577,-858.49 h60
Drill Drawing:
  circle w10: c8443.72,2538.36 r27.63
  lines w10: 8416.09,2400.23 8429.9,2400.23 8429.9,2386.42 8457.53,2386.42 8457.53,2400.23 8471.34,2400.23 8471.34,2427.86 8457.53,2427.86 8457.53,2441.67 8429.9,2441.67 8429.9,2427.86 8416.09,2427.86 8416.09,2400.23 ; 8416.09,2635.06 8443.72,2648.87 8471.34,2635.06 8457.53,2662.68 8471.34,2690.31 8443.72,2676.5 8416.09,2690.31 8429.9,2662.68 8416.09,2635.06 ; 8416.09,2814.63 8471.34,2814.63 8443.72,2759.38 8416.09,2814.63 ; 8416.09,2883.7 8416.09,2897.51 8429.9,2911.32 8416.09,2925.14 8416.09,2938.95 8429.9,2938.95 8443.72,2925.14 8457.53,2938.95 8471.34,2938.95 8471.34,2925.14 8457.53,2911.32 8471.34,2897.51 8471.34,2883.7 8457.53,2883.7 8443.72,2897.51 8429.9,2883.7 8416.09,2883.7 ; 8416.09,3008.02 8471.34,3008.02 8471.34,3063.27 8416.09,3063.27 8416.09,3008.02 ; 8416.09,3159.96 8443.72,3132.34 8471.34,3159.96 8443.72,3187.59 8416.09,3159.96 ; 8416.09,3270.47 8429.9,3270.47 8443.72,3256.66 8457.53,3270.47 8471.34,3270.47 8457.53,3284.28 8471.34,3298.1 8457.53,3298.1 8443.72,3311.91 8429.9,3298.1 8416.09,3298.1 8429.9,3284.28 8416.09,3270.47
  lines w12: 8366,2349.12 11597.49,2349.12 ; 8366,3343.68 11597.49,3343.68 ; 8703.86,2224.8 8703.86,3468 ; 9035.86,2224.8 9035.86,3468 ; 9672.43,2224.8 9672.43,3468 ; 9931.57,2224.8 9931.57,3468 ; 10306.72,2224.8 10306.72,3468 ; 11031.05,2224.8 11031.05,3468 ; 8366,2224.8 11597.49,2224.8 11597.49,3468 8366,3468 8366,2224.8
  text "Symbol" at 8440.59,3380.98 h72
  text "Quantity" at 8741.16,3380.98 h72
  text "Finished Hole Size" at 9073.16,3380.98 h72
  text "Plated" at 9709.72,3380.98 h72
  text "Hole Type" at 9968.86,3380.98 h72
  text "Drill Layer Pair" at 10344.02,3380.98 h72
  text "Hole Tolerance" at 11068.35,3380.98 h72
  text "8" at 8741.16,3256.66 h60
  text "7.87mil (0.200mm)" at 9073.16,3256.66 h60
  text "PTH" at 9709.72,3256.66 h60
  text "Round" at 9968.86,3256.66 h60
  text "Top Layer - Bottom Layer" at 10344.02,3256.66 h60
  text "159" at 8741.16,3132.34 h60
  text "8.00mil (0.203mm)" at 9073.16,3132.34 h60
  text "PTH" at 9709.72,3132.34 h60
  text "Round" at 9968.86,3132.34 h60
  text "Top Layer - Bottom Layer" at 10344.02,3132.34 h60
  text "623" at 8741.16,3008.02 h60
  text "12.00mil (0.305mm)" at 9073.16,3008.02 h60
  text "PTH" at 9709.72,3008.02 h60
  text "Round" at 9968.86,3008.02 h60
  text "Top Layer - Bottom Layer" at 10344.02,3008.02 h60
  text "174" at 8741.16,2883.7 h60
  text "16.00mil (0.406mm)" at 9073.16,2883.7 h60
  text "PTH" at 9709.72,2883.7 h60
  text "Round" at 9968.86,2883.7 h60
  text "Top Layer - Bottom Layer" at 10344.02,2883.7 h60
  text "4" at 8741.16,2759.38 h60
  text "40.00mil (1.016mm)" at 9073.16,2759.38 h60
  text "PTH" at 9709.72,2759.38 h60
  text "Round" at 9968.86,2759.38 h60
  text "Top Layer - Bottom Layer" at 10344.02,2759.38 h60
  text "10" at 8741.16,2635.06 h60
  text "63.00mil (1.600mm)" at 9073.16,2635.06 h60
  text "PTH" at 9709.72,2635.06 h60
  text "Round" at 9968.86,2635.06 h60
  text "Top Layer - Bottom Layer" at 10344.02,2635.06 h60
  text "4" at 8741.16,2510.74 h60
  text "125.98mil (3.200mm)" at 9073.16,2510.74 h60
  text "PTH" at 9709.72,2510.74 h60
  text "Round" at 9968.86,2510.74 h60
  text "Top Layer - Bottom Layer" at 10344.02,2510.74 h60
  text "3" at 8741.16,2386.42 h60
  text "254.00mil (6.452mm)" at 9073.16,2386.42 h60
  text "PTH" at 9709.72,2386.42 h60
  text "Round" at 9968.86,2386.42 h60
  text "Top Layer - Bottom Layer" at 10344.02,2386.42 h60
  text "985 Total" at 8741.16,2262.1 h60
  text ".Layer_Name" at 577,-858.49 h60
M17 Embedded Cavity:
  text ".Layer_Name" at 577,-858.49 h60
M18 Embedded Assembly:
  text ".Layer_Name" at 577,-858.49 h60
M19 Embedded Keepout:
  text ".Layer_Name" at 567,-858.49 h60

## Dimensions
0,0 to 0,3400 on M2 Board Dimensions
0,0 to 5200,0 on M2 Board Dimensions
0,-400 to 1000,-400 on M2 Board Dimensions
